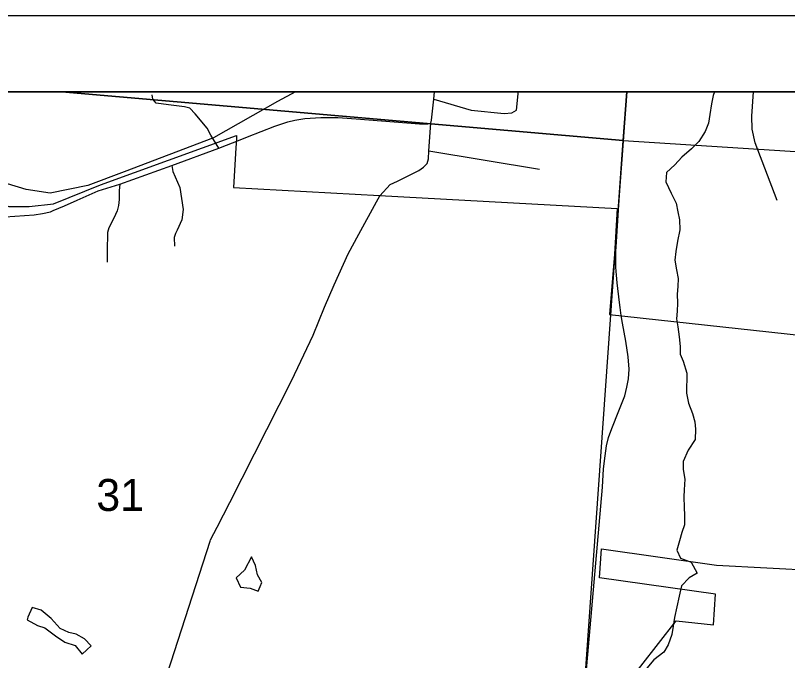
# Model space of a CAD drawing. Extents: x 0 to 34, y 0 to 22.
# Drawn here: x 26.707 to 27.717, y 20.156 to 21 of the extents above; entities that cross this region are included whole.
import ezdxf

# ---------------------------------------------------------------- set-up
doc = ezdxf.new("R2010")
doc.units = 0
for name, color, linetype in [('GM_X_City_Street', 7, 'Continuous'), ('GM_X_Corporation', 7, 'Continuous'), ('GM_X_County_Road', 7, 'Continuous'), ('GM_X_Minor_Lake', 7, 'Continuous'), ('GM_X_Minor_River', 7, 'Continuous'), ('GM_X_Rail_Line', 7, 'Continuous'), ('GM_X_Section_Text', 7, 'Continuous'), ('GM_X_State_Route', 7, 'Continuous'), ('GM_X_Township_Road', 7, 'Continuous'), ('SH_Data', 7, 'Continuous')]:
    doc.layers.add(name, color=color, linetype=linetype)

msp = doc.modelspace()

# ---------------------------------------------------------------- linework, layer by layer
at = {"layer": 'GM_X_City_Street'}
msp.add_line((27.2477, 20.8228), (27.3926, 20.7988), dxfattribs=at)
for points in [[(27.2542, 20.8903), (27.3032, 20.8762), (27.346, 20.8719), (27.3561, 20.8724), (27.3622, 20.8763), (27.3643, 20.8976), (27.3643, 20.9)], [(27.7035, 20.7578), (27.6747, 20.8335), (27.6706, 20.8513), (27.6703, 20.8683), (27.6723, 20.9)], [(27.1833, 20.764), (27.197, 20.7787), (27.2068, 20.7834), (27.2345, 20.7971), (27.2406, 20.8014), (27.2454, 20.8064), (27.2472, 20.8125), (27.2477, 20.8228), (27.2502, 20.8591)]]:
    msp.add_lwpolyline(points, dxfattribs=at)
at = {"layer": 'GM_X_Corporation'}
for points in [[(26.7674, 20.9), (26.378, 20.9), (26.302, 19.9328), (27.3834, 19.8411), (27.4311, 19.8373), (27.5018, 20.8365)], [(27.5066, 20.9), (26.7674, 20.9), (27.5018, 20.8365)], [(28.5537, 20.9), (27.5066, 20.9), (27.5018, 20.8365), (28.5465, 20.7695)], [(27.5018, 20.8365), (28.5465, 20.7695), (28.4917, 19.7627), (28.3876, 19.7694), (27.4311, 19.8373)]]:
    msp.add_lwpolyline(points, close=True, dxfattribs=at)
for points in [[(30.3167, 20.9), (26.3743, 20.9), (26.3351, 20.3683), (26.3029, 19.931), (26.7956, 19.89), (26.8828, 19.8806), (26.9103, 19.8778), (27.1108, 19.8614), (27.3234, 19.8454), (27.4349, 19.8368), (27.4932, 19.8346), (27.6007, 19.8241), (27.7009, 19.814), (27.713, 19.8126), (27.7479, 19.8098)], [(28.9263, 20.9), (26.5396, 20.9), (26.5419, 20.8872), (26.5693, 20.8261), (26.602, 20.7901), (26.6377, 20.7711), (26.6659, 20.7596), (26.6978, 20.75), (26.7246, 20.7499), (26.7565, 20.7536), (26.8179, 20.7785), (26.9961, 20.8428), (26.9958, 20.8386), (26.9952, 20.827), (26.9921, 20.775), (27.1831, 20.7645), (27.4939, 20.7474), (27.4907, 20.6875), (27.484, 20.6087), (27.7367, 20.5812)], [(27.7377, 20.0262), (27.6953, 19.9588), (27.6811, 19.8396), (27.6576, 19.8303), (27.6007, 19.8271), (27.6007, 19.8241), (27.5679, 19.8271), (27.4932, 19.8346), (27.4932, 19.8804), (27.4932, 20.0054), (27.4919, 20.0789), (27.502, 20.1192), (27.5714, 20.208), (27.6201, 20.2028), (27.6229, 20.2429), (27.4708, 20.2643), (27.4734, 20.3021), (27.624, 20.2809), (27.9533, 20.2636)]]:
    msp.add_lwpolyline(points, dxfattribs=at)
at = {"layer": 'GM_X_County_Road'}
for points in [[(26.987, 20.363), (27.0679, 20.5222), (27.0964, 20.5819), (27.111, 20.6186), (27.1236, 20.6477), (27.1421, 20.6883), (27.1558, 20.7139), (27.1791, 20.7562), (27.1833, 20.764)], [(26.797, 19.8922), (26.8016, 19.9024), (26.8198, 19.9372), (26.8631, 20.0188), (26.8868, 20.0815), (26.9614, 20.3123), (26.962, 20.314), (26.9705, 20.3306), (26.987, 20.363)]]:
    msp.add_lwpolyline(points, dxfattribs=at)
at = {"layer": 'GM_X_Minor_Lake'}
for points in [[(27.0154, 20.2917), (27.0063, 20.2743), (26.9953, 20.2645), (27.0013, 20.252), (27.0138, 20.2508), (27.0244, 20.247), (27.0268, 20.253)], [(27.0268, 20.253), (27.029, 20.2584), (27.0233, 20.2682), (27.0207, 20.2804), (27.0154, 20.2917)], [(26.7999, 20.1701), (26.8056, 20.1752), (26.7969, 20.1847), (26.7863, 20.1908), (26.7765, 20.1927), (26.7652, 20.198), (26.7535, 20.2113), (26.7402, 20.2219), (26.7285, 20.2257), (26.7228, 20.2129)], [(26.7228, 20.2129), (26.7221, 20.2094), (26.7353, 20.2018), (26.7451, 20.1988), (26.7591, 20.1885), (26.7712, 20.1802), (26.7848, 20.1756), (26.7939, 20.1646), (26.7999, 20.1701)]]:
    msp.add_lwpolyline(points, dxfattribs=at)
at = {"layer": 'GM_X_Minor_River'}
for points in [[(27.6214, 20.9), (27.6198, 20.8951), (27.6175, 20.8844), (27.6155, 20.8704), (27.6135, 20.8591), (27.6093, 20.8481), (27.6009, 20.8349), (27.5914, 20.8255), (27.5788, 20.8146), (27.5696, 20.8044), (27.5586, 20.7946), (27.5578, 20.7825), (27.5649, 20.7676), (27.5712, 20.7543), (27.5734, 20.7433), (27.5756, 20.7327), (27.5759, 20.7194), (27.5731, 20.7046)], [(27.5731, 20.7046), (27.5708, 20.6914), (27.5696, 20.68), (27.5717, 20.6671), (27.5739, 20.6557), (27.5735, 20.6454), (27.5727, 20.6352), (27.573, 20.6238), (27.5725, 20.6132), (27.5717, 20.603), (27.5735, 20.5927), (27.5753, 20.5794), (27.5764, 20.5669), (27.5763, 20.5571), (27.5804, 20.5476), (27.5852, 20.532), (27.585, 20.5058), (27.5876, 20.4929), (27.5928, 20.4792), (27.5957, 20.4682), (27.5968, 20.4587), (27.5963, 20.4454), (27.5872, 20.4315), (27.5806, 20.4163), (27.5806, 20.4061), (27.5827, 20.3932), (27.5819, 20.3795), (27.5811, 20.3701), (27.5817, 20.3564), (27.5824, 20.3462), (27.582, 20.3337), (27.5789, 20.3234), (27.5758, 20.3128), (27.5723, 20.3003), (27.5771, 20.2901), (27.5907, 20.285), (27.5989, 20.2706), (27.5883, 20.2642), (27.5784, 20.254), (27.5753, 20.2404), (27.569, 20.2124), (27.5674, 20.201), (27.5655, 20.19), (27.5608, 20.1768), (27.5551, 20.167), (27.5422, 20.1572), (27.533, 20.1462)]]:
    msp.add_lwpolyline(points, dxfattribs=at)
at = {"layer": 'GM_X_Rail_Line'}
msp.add_lwpolyline([(27.0732, 20.9), (27.0496, 20.8875), (26.9657, 20.8399), (26.849, 20.7955), (26.8013, 20.7774), (26.752, 20.7675), (26.7208, 20.7725), (26.6715, 20.7873), (26.6106, 20.8201), (26.5876, 20.8448), (26.5794, 20.8826), (26.5736, 20.9)], dxfattribs=at)
at = {"layer": 'GM_X_State_Route'}
for p, q in [((27.4967, 20.7583), (27.4981, 20.777)), ((27.4966, 20.7573), (27.4967, 20.7583))]:
    msp.add_line(p, q, dxfattribs=at)
for points in [[(27.2502, 20.8591), (27.2512, 20.8631), (27.2542, 20.8903), (27.2551, 20.9)], [(27.4981, 20.777), (27.5006, 20.8115), (27.5063, 20.8898), (27.507, 20.9)], [(27.0009, 20.8375), (27.0103, 20.8413), (27.046, 20.8551), (27.063, 20.861), (27.0724, 20.8632), (27.0852, 20.8654), (27.1062, 20.8666), (27.1286, 20.8665), (27.1526, 20.8649), (27.1689, 20.8636)], [(27.1689, 20.8636), (27.2354, 20.8583), (27.2463, 20.8582), (27.2502, 20.8591)], [(26.8433, 20.7794), (26.9112, 20.8035), (26.9726, 20.8262), (27.0009, 20.8375)], [(26.7872, 20.7583), (26.8147, 20.7707), (26.8433, 20.7794)], [(26.366, 20.3881), (26.4127, 20.4221), (26.4402, 20.4511), (26.4616, 20.4899), (26.512, 20.6439), (26.5269, 20.6833), (26.5343, 20.6931), (26.5514, 20.7118), (26.5666, 20.7266), (26.5765, 20.734), (26.5893, 20.7369), (26.6065, 20.7366), (26.6931, 20.7364), (26.731, 20.7392), (26.7422, 20.741), (26.7525, 20.7433), (26.7558, 20.7447), (26.7707, 20.751), (26.7872, 20.7583)], [(27.4929, 20.6972), (27.4963, 20.7524), (27.4966, 20.7573)], [(27.501, 20.5975), (27.4991, 20.6073), (27.498, 20.6178), (27.4972, 20.6245), (27.494, 20.6503), (27.493, 20.6601), (27.4922, 20.6705), (27.4925, 20.6912), (27.4929, 20.6972)], [(27.4351, 19.8363), (27.4549, 19.9142), (27.4606, 19.9384), (27.4598, 19.9597), (27.4561, 19.9782), (27.4508, 20.0025), (27.4472, 20.0181), (27.4458, 20.0447), (27.4477, 20.0745), (27.4747, 20.3831), (27.4763, 20.4068), (27.4782, 20.4239), (27.48, 20.4369), (27.4828, 20.448), (27.4869, 20.4597), (27.4963, 20.4829), (27.5039, 20.5023), (27.5068, 20.5138), (27.5088, 20.5248), (27.5096, 20.5372), (27.5085, 20.5533), (27.5055, 20.574), (27.501, 20.5975)]]:
    msp.add_lwpolyline(points, dxfattribs=at)
at = {"layer": 'GM_X_Township_Road'}
for points in [[(26.9726, 20.8262), (26.9623, 20.8436), (26.9575, 20.8526), (26.9417, 20.8713), (26.9348, 20.8785), (26.9279, 20.8806), (26.9071, 20.8832), (26.8907, 20.8851), (26.8866, 20.8903), (26.8857, 20.8961)], [(26.9112, 20.8035), (26.9127, 20.7958), (26.9216, 20.775), (26.926, 20.746), (26.9245, 20.7327), (26.9181, 20.7189), (26.916, 20.7147), (26.9143, 20.7095), (26.9147, 20.6981)], [(26.8433, 20.7794), (26.8422, 20.7711), (26.8424, 20.7591), (26.8417, 20.7512), (26.8396, 20.7445), (26.8355, 20.735), (26.8288, 20.7223), (26.8269, 20.7161), (26.8268, 20.6916), (26.8267, 20.6773)]]:
    msp.add_lwpolyline(points, dxfattribs=at)
at = {"layer": 'SH_Data'}
for points in [[(23.4167, 21), (30.4167, 21), (30.4167, 14), (23.4167, 14)], [(23.5167, 20.9), (30.3167, 20.9), (30.3167, 14.1), (23.5167, 14.1)]]:
    msp.add_lwpolyline(points, close=True, dxfattribs=at)

# ---------------------------------------------------------------- texts
at = {"layer": 'GM_X_Section_Text'}
msp.add_text('31', height=0.04186, rotation=0, dxfattribs=at).set_placement((26.8125, 20.3518))

doc.saveas('drawing.dxf')
